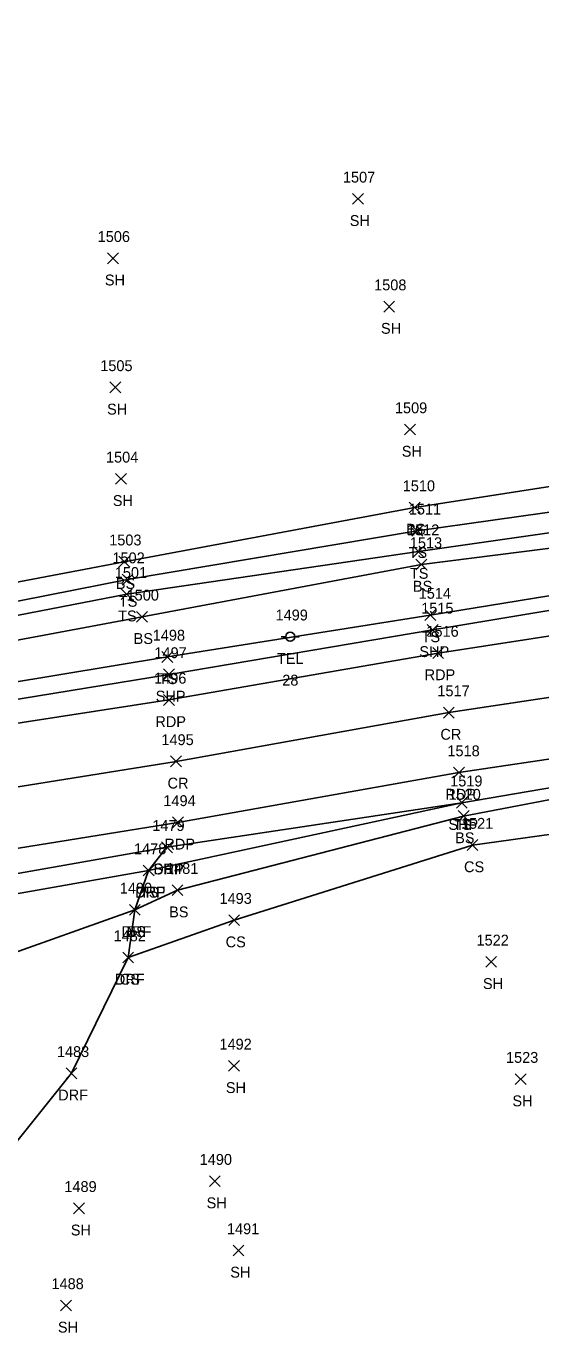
# Model space of a CAD drawing. Extents: x 1497084 to 1499861, y 734741 to 735567.
# Drawn here: x 1499028.5 to 1499123.3, y 735313.5 to 735555 of the extents above; entities that cross this region are included whole.
import ezdxf

# ---------------------------------------------------------------- set-up
doc = ezdxf.new("R2010")
doc.units = 0
for name, color, linetype in [('L_A', 7, 'Continuous'), ('L_I', 7, 'Continuous'), ('L_TIC', 7, 'Continuous'), ('LELB', 7, 'Continuous'), ('P_A', 7, 'Continuous'), ('P_I', 7, 'Continuous'), ('P_TIC', 7, 'Continuous'), ('PET', 7, 'Continuous'), ('PRC', 7, 'Continuous'), ('PSP', 7, 'Continuous'), ('R_A', 7, 'Continuous'), ('R_I', 7, 'Continuous'), ('R_TIC', 7, 'Continuous'), ('RDF', 7, 'Continuous'), ('RDP', 7, 'Continuous'), ('U_A', 7, 'Continuous'), ('U_C', 7, 'Continuous'), ('U_I', 7, 'Continuous'), ('UP', 7, 'Continuous')]:
    doc.layers.add(name, color=color, linetype=linetype)

msp = doc.modelspace()

# ---------------------------------------------------------------- linework, layer by layer
at = {"layer": 'L_TIC'}
for points in [[(1499088.6, 735522.25), (1499090.6, 735524.25)], [(1499090.6, 735522.25), (1499088.6, 735524.25)], [(1499043.48, 735511.31), (1499045.48, 735513.31)], [(1499045.48, 735511.31), (1499043.48, 735513.31)], [(1499094.34, 735502.4), (1499096.34, 735504.4)], [(1499096.34, 735502.4), (1499094.34, 735504.4)], [(1499043.89, 735487.52), (1499045.89, 735489.52)], [(1499045.89, 735487.52), (1499043.89, 735489.52)], [(1499098.18, 735479.76), (1499100.18, 735481.76)], [(1499100.18, 735479.76), (1499098.18, 735481.76)], [(1499044.95, 735470.68), (1499046.95, 735472.68)], [(1499046.95, 735470.68), (1499044.95, 735472.68)], [(1499099.05, 735465.4), (1499101.05, 735467.4)], [(1499101.05, 735465.4), (1499099.05, 735467.4)], [(1499099.52, 735461.11), (1499101.52, 735463.11)], [(1499101.52, 735461.11), (1499099.52, 735463.11)], [(1499099.75, 735457.28), (1499101.75, 735459.28)], [(1499101.75, 735457.28), (1499099.75, 735459.28)], [(1499045.55, 735455.42), (1499047.55, 735457.42)], [(1499047.55, 735455.42), (1499045.55, 735457.42)], [(1499100.27, 735454.9), (1499102.27, 735456.9)], [(1499102.27, 735454.9), (1499100.27, 735456.9)], [(1499046.14, 735452.13), (1499048.14, 735454.13)], [(1499048.14, 735452.13), (1499046.14, 735454.13)], [(1499046, 735449.43), (1499048, 735451.43)], [(1499048, 735449.43), (1499046, 735451.43)], [(1499048.83, 735445.27), (1499050.83, 735447.27)], [(1499050.83, 735445.27), (1499048.83, 735447.27)], [(1499101.91, 735445.6), (1499103.91, 735447.6)], [(1499103.91, 735445.6), (1499101.91, 735447.6)], [(1499053.48, 735437.88), (1499055.48, 735439.88)], [(1499055.48, 735437.88), (1499053.48, 735439.88)], [(1499107.72, 735411.03), (1499109.72, 735413.03)], [(1499109.72, 735411.03), (1499107.72, 735413.03)], [(1499108.05, 735408.57), (1499110.05, 735410.57)], [(1499110.05, 735408.57), (1499108.05, 735410.57)], [(1499109.69, 735403.23), (1499111.69, 735405.23)], [(1499111.69, 735403.23), (1499109.69, 735405.23)], [(1499050.03, 735398.55), (1499052.03, 735400.55)], [(1499052.03, 735398.55), (1499050.03, 735400.55)], [(1499055.36, 735394.92), (1499057.36, 735396.92)], [(1499057.36, 735394.92), (1499055.36, 735396.92)], [(1499047.5, 735391.29), (1499049.5, 735393.29)], [(1499049.5, 735391.29), (1499047.5, 735393.29)], [(1499065.78, 735389.4), (1499067.78, 735391.4)], [(1499067.78, 735389.4), (1499065.78, 735391.4)], [(1499046.27, 735382.52), (1499048.27, 735384.52)], [(1499048.27, 735382.52), (1499046.27, 735384.52)], [(1499113.12, 735381.72), (1499115.12, 735383.72)], [(1499115.12, 735381.72), (1499113.12, 735383.72)], [(1499065.77, 735362.56), (1499067.77, 735364.56)], [(1499067.77, 735362.56), (1499065.77, 735364.56)], [(1499118.55, 735360.12), (1499120.55, 735362.12)], [(1499120.55, 735360.12), (1499118.55, 735362.12)], [(1499062.22, 735341.33), (1499064.22, 735343.33)], [(1499064.22, 735341.33), (1499062.22, 735343.33)], [(1499037.21, 735336.33), (1499039.21, 735338.33)], [(1499039.21, 735336.33), (1499037.21, 735338.33)], [(1499066.58, 735328.56), (1499068.58, 735330.56)], [(1499068.58, 735328.56), (1499066.58, 735330.56)], [(1499034.83, 735318.44), (1499036.83, 735320.44)], [(1499036.83, 735318.44), (1499034.83, 735320.44)]]:
    msp.add_lwpolyline(points, dxfattribs=at)
at = {"layer": 'LELB'}
for points in [[(1498873.92, 735413.56), (1498885.61, 735419.45), (1498937.6, 735431.47), (1498992.42, 735446.17), (1499046.55, 735456.42), (1499100.05, 735466.4), (1499155.3, 735475.02), (1499211.81, 735485.81), (1499272.89, 735498.35), (1499312.63, 735498.22), (1499378.23, 735496.87), (1499423.72, 735498.7), (1499448.77, 735497.16), (1499468.03, 735503.5), (1499479.61, 735506.38), (1499485.8, 735535.79), (1499495.73, 735555.05)], [(1498887.06, 735413.08), (1498886.64, 735416.64), (1498937.22, 735426.43), (1498992.82, 735439.97), (1499047, 735450.43), (1499100.75, 735458.28), (1499155.76, 735466.18), (1499214.75, 735478.18), (1499272.85, 735494.27), (1499312.36, 735493.24), (1499378.42, 735492.78), (1499423.87, 735493.47), (1499447.7, 735493.36), (1499467.98, 735499.39), (1499480.88, 735502.15), (1499491.75, 735532.72), (1499501.47, 735549.91)], [(1498866.36, 735448.26), (1498857.15, 735430.71), (1498857.91, 735411.98), (1498873.92, 735413.56), (1498887.06, 735413.08), (1498937.75, 735422.9), (1498993.01, 735435.64), (1499049.83, 735446.27), (1499101.27, 735455.9), (1499156.57, 735462.9), (1499215.64, 735473.1), (1499268.79, 735480.58), (1499268.83, 735484.45), (1499283.35, 735488.28), (1499292.38, 735481.13), (1499315.72, 735484.63), (1499378.98, 735487.71)], [(1498836.02, 735409.82), (1498851.62, 735410.69), (1498873.71, 735408.53), (1498887.41, 735411.13), (1498937.88, 735419.58), (1498994.04, 735428.91), (1499054.48, 735438.88), (1499102.91, 735446.6), (1499157.52, 735455.49), (1499217.09, 735464.03), (1499265.79, 735469.16), (1499273.78, 735473.78), (1499316.12, 735477.44), (1499378.42, 735481.09), (1499425.85, 735484.53), (1499445.24, 735487.28), (1499459.87, 735483.77), (1499494.5, 735481.39), (1499511.88, 735480.66), (1499514.4, 735477.39)], [(1498937.22, 735426.43), (1498937.39, 735427.9), (1498992.7, 735442.42), (1499047.14, 735453.13), (1499100.52, 735462.11), (1499156.22, 735469.96), (1499214.75, 735478.18)], [(1498902.07, 735368.05), (1498907.17, 735371.51), (1498940.32, 735377.55), (1498999.63, 735387.02), (1499017.69, 735389.23), (1499022.6, 735383.12), (1499048.5, 735392.29), (1499056.36, 735395.92), (1499109.05, 735409.57), (1499159.67, 735419.26), (1499225.84, 735428.89), (1499272.31, 735428.88), (1499323.36, 735436.06), (1499376.02, 735439.69), (1499385.74, 735428.35), (1499408.33, 735432.03), (1499419.24, 735438.19), (1499448.18, 735438.04), (1499493.15, 735436.77), (1499505.9, 735439.37), (1499516.74, 735441.77), (1499516.38, 735446.4), (1499513.83, 735450.64)], [(1499047.27, 735383.52), (1499066.78, 735390.4), (1499110.69, 735404.23), (1499164.91, 735411.78), (1499229.89, 735424.14), (1499272.31, 735428.88), (1499323.85, 735428.64), (1499384.64, 735421.78), (1499405.49, 735421.31)], [(1499051.03, 735399.55), (1499108.72, 735412.03)]]:
    msp.add_lwpolyline(points, dxfattribs=at)
at = {"layer": 'P_TIC'}
for points in [[(1499102.37, 735442.86), (1499104.37, 735444.86)], [(1499104.37, 735442.86), (1499102.37, 735444.86)], [(1499103.38, 735438.6), (1499105.38, 735440.6)], [(1499105.38, 735438.6), (1499103.38, 735440.6)], [(1499053.79, 735434.66), (1499055.79, 735436.66)], [(1499055.79, 735434.66), (1499053.79, 735436.66)], [(1499053.78, 735429.96), (1499055.78, 735431.96)], [(1499055.78, 735429.96), (1499053.78, 735431.96)], [(1499105.34, 735427.63), (1499107.34, 735429.63)], [(1499107.34, 735427.63), (1499105.34, 735429.63)], [(1499055.08, 735418.64), (1499057.08, 735420.64)], [(1499057.08, 735418.64), (1499055.08, 735420.64)], [(1499107.2, 735416.59), (1499109.2, 735418.59)], [(1499109.2, 735416.59), (1499107.2, 735418.59)], [(1499107.72, 735411.03), (1499109.72, 735413.03)], [(1499109.72, 735411.03), (1499107.72, 735413.03)], [(1499055.44, 735407.41), (1499057.44, 735409.41)], [(1499057.44, 735407.41), (1499055.44, 735409.41)], [(1499053.41, 735402.83), (1499055.41, 735404.83)], [(1499055.41, 735402.83), (1499053.41, 735404.83)]]:
    msp.add_lwpolyline(points, dxfattribs=at)
at = {"layer": 'PET'}
for points in [[(1498838.32, 735395.91), (1498888.99, 735404.3), (1498938.22, 735411.59), (1498994.69, 735421.68), (1499054.78, 735430.96), (1499104.38, 735439.6), (1499157.66, 735447.8), (1499219.31, 735457.47), (1499265.92, 735463.89), (1499317.31, 735469.95), (1499378.29, 735473.92), (1499424.75, 735475.7), (1499462.5, 735476.09), (1499495.09, 735475.96), (1499513.91, 735475.18)], [(1498842.44, 735373.21), (1498892.67, 735381.87), (1498940.26, 735389.17), (1498997.67, 735398.94), (1499056.44, 735408.41), (1499108.2, 735417.59), (1499160.18, 735425.34), (1499224.61, 735435.78), (1499269.11, 735441.52), (1499319.5, 735447.91), (1499378.39, 735452.04), (1499424.16, 735454.42), (1499461.26, 735454.74), (1499493.51, 735454.63), (1499512.44, 735453.4), (1499513.2, 735464.25), (1499513.91, 735475.18)]]:
    msp.add_lwpolyline(points, dxfattribs=at)
at = {"layer": 'PRC'}
msp.add_lwpolyline([(1498839.89, 735384.37), (1498890.74, 735392.79), (1498939.31, 735400.24), (1498995.85, 735410.01), (1499056.08, 735419.64), (1499106.34, 735428.63), (1499159.02, 735436.58), (1499221.74, 735447.44), (1499267.15, 735453.23), (1499318.55, 735459.5), (1499378.61, 735463.51), (1499424.29, 735465.34), (1499461.73, 735465.4), (1499494.05, 735465.28), (1499513.2, 735464.25)], dxfattribs=at)
at = {"layer": 'PSP'}
for points in [[(1498833.8, 735399.85), (1498855.6, 735403.69), (1498873.7, 735405.84), (1498888.17, 735408.98), (1498937.73, 735416.37), (1498993.87, 735425.67), (1499054.79, 735435.66), (1499103.37, 735443.86), (1499157.46, 735452.91), (1499218.03, 735462.22), (1499265.79, 735469.16), (1499316.87, 735474.83), (1499378.34, 735479.55), (1499425.23, 735479.95), (1499462.88, 735477.81), (1499495.09, 735475.96)], [(1498843.61, 735368.57), (1498860.46, 735371.23), (1498865.28, 735372.42), (1498905.37, 735378.8), (1498940.19, 735384.06), (1498998.48, 735394.31), (1499018.85, 735397.58), (1499054.41, 735403.83), (1499108.72, 735412.03), (1499160.14, 735420.81), (1499224.87, 735431.1), (1499270.68, 735437.25), (1499320.13, 735443.34), (1499381.94, 735448.71), (1499417.25, 735450.68), (1499461.26, 735454.74)]]:
    msp.add_lwpolyline(points, dxfattribs=at)
at = {"layer": 'R_TIC'}
for points in [[(1499053.41, 735402.83), (1499055.41, 735404.83)], [(1499055.41, 735402.83), (1499053.41, 735404.83)], [(1499050.03, 735398.55), (1499052.03, 735400.55)], [(1499052.03, 735398.55), (1499050.03, 735400.55)], [(1499050.03, 735398.55), (1499052.03, 735400.55)], [(1499052.03, 735398.55), (1499050.03, 735400.55)], [(1499047.5, 735391.29), (1499049.5, 735393.29)], [(1499049.5, 735391.29), (1499047.5, 735393.29)], [(1499046.27, 735382.52), (1499048.27, 735384.52)], [(1499048.27, 735382.52), (1499046.27, 735384.52)], [(1499035.84, 735361.19), (1499037.84, 735363.19)], [(1499037.84, 735361.19), (1499035.84, 735363.19)]]:
    msp.add_lwpolyline(points, dxfattribs=at)
at = {"layer": 'RDF'}
msp.add_lwpolyline([(1499051.03, 735399.55), (1499048.5, 735392.29), (1499047.27, 735383.52), (1499036.84, 735362.19), (1499017.88, 735338.59), (1499008.05, 735313.48)], dxfattribs=at)
at = {"layer": 'RDP'}
msp.add_lwpolyline([(1499018.85, 735397.58), (1499022.1, 735394.44), (1499051.03, 735399.55), (1499054.41, 735403.83)], dxfattribs=at)
at = {"layer": 'UP'}
for p, q in [((1499075.45, 735442.6), (1499076.28, 735442.6)), ((1499077.11, 735442.6), (1499077.11, 735442.6)), ((1499078.78, 735442.6), (1499077.95, 735442.6)), ((1499077.95, 735442.6), (1499077.95, 735442.6)), ((1499078.78, 735442.6), (1499078.78, 735442.6))]:
    msp.add_line(p, q, dxfattribs=at)
msp.add_circle((1499077.11, 735442.6), 0.833, dxfattribs=at)

# ---------------------------------------------------------------- texts
at = {"layer": 'L_A'}
for s, p in [('SH', (1499088.08, 735518.25)), ('SH', (1499042.97, 735507.31)), ('SH', (1499093.83, 735498.4)), ('SH', (1499043.38, 735483.52)), ('SH', (1499097.67, 735475.76)), ('SH', (1499044.44, 735466.68)), ('BS', (1499098.49, 735461.4)), ('TS', (1499098.92, 735457.11)), ('TS', (1499099.16, 735453.28)), ('BS', (1499044.99, 735451.42)), ('BS', (1499099.71, 735450.9)), ('TS', (1499045.55, 735448.13)), ('TS', (1499045.41, 735445.43)), ('BS', (1499048.27, 735441.27)), ('TS', (1499101.31, 735441.6)), ('TS', (1499052.89, 735433.88)), ('TS', (1499107.13, 735407.03)), ('BS', (1499107.49, 735404.57)), ('CS', (1499109.13, 735399.23)), ('TS', (1499049.44, 735394.55)), ('BS', (1499054.81, 735390.92)), ('BS', (1499046.95, 735387.29)), ('CS', (1499065.22, 735385.4)), ('CS', (1499045.71, 735378.52)), ('SH', (1499112.61, 735377.72)), ('SH', (1499065.26, 735358.56)), ('SH', (1499118.04, 735356.12)), ('SH', (1499061.71, 735337.33)), ('SH', (1499036.7, 735332.33)), ('SH', (1499066.07, 735324.56)), ('SH', (1499034.32, 735314.44))]:
    msp.add_text(s, height=2, dxfattribs=at).set_placement(p)
at = {"layer": 'L_I'}
for s, p in [('1507', (1499086.82, 735526.25)), ('1506', (1499041.65, 735515.31)), ('1508', (1499092.57, 735506.4)), ('1505', (1499042.12, 735491.52)), ('1509', (1499096.4, 735483.76)), ('1504', (1499043.18, 735474.68)), ('1510', (1499097.84, 735469.4)), ('1511', (1499098.96, 735465.11)), ('1503', (1499043.77, 735459.42)), ('1512', (1499098.62, 735461.28)), ('1513', (1499099.15, 735458.9)), ('1502', (1499044.37, 735456.13)), ('1501', (1499044.8, 735453.43)), ('1500', (1499046.98, 735449.27)), ('1514', (1499100.78, 735449.6)), ('1498', (1499051.79, 735441.88)), ('1519', (1499106.58, 735415.03)), ('1520', (1499106.27, 735412.57)), ('1521', (1499108.56, 735407.23)), ('1478', (1499048.34, 735402.55)), ('1481', (1499054.24, 735398.92)), ('1480', (1499045.72, 735395.29)), ('1493', (1499064.09, 735393.4)), ('1482', (1499044.58, 735386.52)), ('1522', (1499111.43, 735385.72)), ('1492', (1499064.08, 735366.56)), ('1523', (1499116.86, 735364.12)), ('1490', (1499060.44, 735345.33)), ('1489', (1499035.51, 735340.33)), ('1491', (1499065.46, 735332.56)), ('1488', (1499033.14, 735322.44))]:
    msp.add_text(s, height=2, dxfattribs=at).set_placement(p)
at = {"layer": 'P_A'}
for s, p in [('SHP', (1499100.9, 735438.86)), ('RDP', (1499101.87, 735434.6)), ('SHP', (1499052.33, 735430.66)), ('RDP', (1499052.27, 735425.96)), ('CR', (1499104.78, 735423.63)), ('CR', (1499054.52, 735414.64)), ('RDP', (1499105.69, 735412.59)), ('SHP', (1499106.25, 735407.03)), ('RDP', (1499053.93, 735403.41)), ('SHP', (1499051.95, 735398.83))]:
    msp.add_text(s, height=2, dxfattribs=at).set_placement(p)
at = {"layer": 'P_I'}
for s, p in [('1515', (1499101.24, 735446.86)), ('1516', (1499102.2, 735442.6)), ('1497', (1499052.1, 735438.66)), ('1496', (1499052.04, 735433.96)), ('1517', (1499104.22, 735431.63)), ('1495', (1499053.39, 735422.64)), ('1518', (1499106.07, 735420.59)), ('1519', (1499106.58, 735415.03)), ('1494', (1499053.75, 735411.41)), ('1479', (1499051.71, 735406.83))]:
    msp.add_text(s, height=2, dxfattribs=at).set_placement(p)
at = {"layer": 'R_A'}
for s, p in [('DRP', (1499051.9, 735398.83)), ('DRP', (1499048.52, 735394.55)), ('DRF', (1499048.57, 735394.55)), ('DRF', (1499046.04, 735387.29)), ('DRF', (1499044.81, 735378.52)), ('DRF', (1499034.37, 735357.19))]:
    msp.add_text(s, height=2, dxfattribs=at).set_placement(p)
at = {"layer": 'R_I'}
for s, p in [('1479', (1499051.71, 735406.83)), ('1478', (1499048.34, 735402.55)), ('1478', (1499048.34, 735402.55)), ('1480', (1499045.72, 735395.29)), ('1482', (1499044.58, 735386.52)), ('1483', (1499034.14, 735365.19))]:
    msp.add_text(s, height=2, dxfattribs=at).set_placement(p)
at = {"layer": 'U_A'}
msp.add_text('TEL', height=2, dxfattribs=at).set_placement((1499074.67, 735437.6))
at = {"layer": 'U_C'}
msp.add_text('28', height=2, dxfattribs=at).set_placement((1499075.65, 735433.6))
at = {"layer": 'U_I'}
msp.add_text('1499', height=2, dxfattribs=at).set_placement((1499074.41, 735445.6))

doc.saveas('drawing.dxf')
